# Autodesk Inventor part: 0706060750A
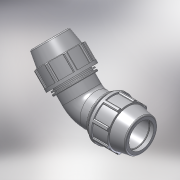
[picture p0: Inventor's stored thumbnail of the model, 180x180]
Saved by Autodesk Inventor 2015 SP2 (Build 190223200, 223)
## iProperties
Created: 2017-02
Part Number: 0706060750A
Material: PVC-Piping
Description: PLASSON 45° ELBOW 75-75
Document SubType Name: Modeling
Designer: KIM
Mass: 92.6774 g
Surface Area: 199.44 cm^2
Volume: 66.1981 cm^3
Density: 1.4 g/cm^3
Appearance: Smooth - White
Author: Кирилл
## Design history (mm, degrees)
derived "87060.ipt"
feature "Solid1::87060.ipt"
tag "TaggingFeature1"
body "Solid1"
other parameters: "d2" = 75, "d4" = 12.75, "d5" = 38.25, "d7" = 134, "d9" = 21.85714, "d11" = 5.1, "d13" = 120 deg, "d14" = 97.5, "d15" = 10 deg, "d16" = 116.58, "d18" = 3.75, "d19" = 35 deg, "d20" = 17.5 deg, "d21" = 124.62, "d23" = 0, "d25" = 360 deg, "d27" = 2.68, "d33" = 1.5, "d42" = 52.02, "d43" = 4.02, "d46" = 1.5, "d51" = 153, "d59" = 135 deg, "d63" = 132, "d64" = 67.5, "d67" = 100.5, "d68" = 9.18, "d70" = 45 deg, "d72" = 8.93333, "d73" = 0, "d75" = 135 deg, "d77" = 114.2484, "d78" = 3.06, "d_" = 75, "E_" = 134, "A_" = 153, "l_" = 132
